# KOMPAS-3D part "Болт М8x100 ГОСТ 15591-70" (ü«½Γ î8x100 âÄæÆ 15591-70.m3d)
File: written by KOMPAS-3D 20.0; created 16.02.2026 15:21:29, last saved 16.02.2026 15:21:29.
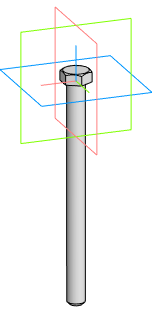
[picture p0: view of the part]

Document properties: Автор: admin; Полное имя файла: P:\INSTART\Технический отдел\ОР\Прочие задачи\КД на номенклатурный ряд\КД на типоразмеры дросселей\Сетевые дроссели ISF\ISF-4\Тип 1\ISF-132_256-4\0723\Новая папка\Болт М8x100 ГОСТ 15591-70.m3d

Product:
- Part/product: Болт М8x100 ГОСТ 15591-70

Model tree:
1. Операция без истории:1  (labels: Болт М8x100 ГОСТ 15591-70)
